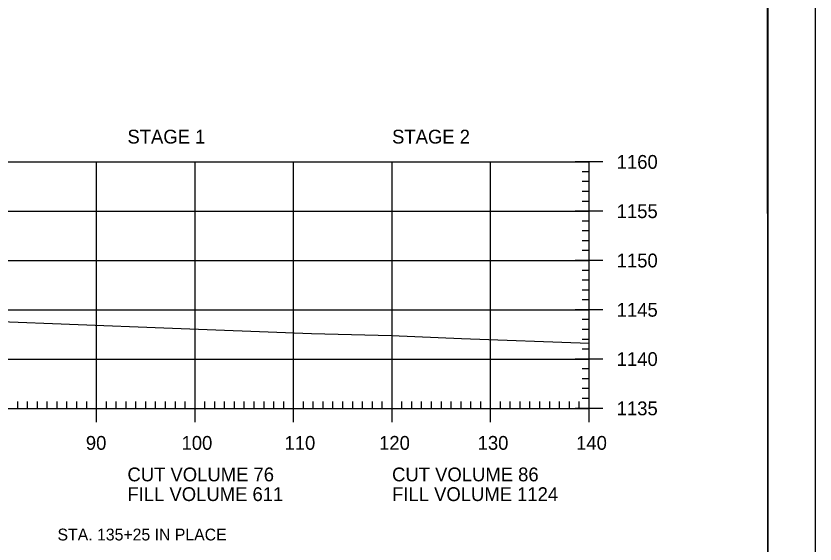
# Model space of a CAD drawing. Extents: x 1322838 to 1324533, y 339903 to 351025.
# Drawn here: x 1323785.5 to 1323866.6, y 342356.1 to 342409.6 of the extents above; entities that cross this region are included whole.
import ezdxf

# ---------------------------------------------------------------- set-up
doc = ezdxf.new("R2010")
doc.units = 0
for name, color, linetype in [('R_Axis', 7, 'Continuous'), ('R_Axis Annot', 7, 'Continuous'), ('R_Border', 7, 'Continuous'), ('R_Border Notes', 7, 'Continuous'), ('R_Exist Surface', 7, 'Continuous'), ('R_Grid', 7, 'Continuous'), ('R_No Plot', 7, 'Continuous')]:
    doc.layers.add(name, color=color, linetype=linetype)

msp = doc.modelspace()

# ---------------------------------------------------------------- linework, layer by layer
at = {"layer": 'R_Axis'}
for p, q in [((1323845.115, 342394.82), (1323842.315, 342394.82)), ((1323843.715, 342369.82), (1323843.715, 342394.82)), ((1323843.715, 342393.82), (1323843.015, 342393.82)), ((1323843.715, 342392.82), (1323843.015, 342392.82)), ((1323843.715, 342391.82), (1323843.015, 342391.82)), ((1323843.715, 342390.82), (1323843.015, 342390.82)), ((1323845.115, 342389.82), (1323842.315, 342389.82)), ((1323843.715, 342388.82), (1323843.015, 342388.82)), ((1323843.715, 342387.82), (1323843.015, 342387.82)), ((1323843.715, 342386.82), (1323843.015, 342386.82)), ((1323843.715, 342385.82), (1323843.015, 342385.82)), ((1323845.115, 342384.82), (1323842.315, 342384.82)), ((1323843.715, 342383.82), (1323843.015, 342383.82)), ((1323843.715, 342382.82), (1323843.015, 342382.82)), ((1323843.715, 342381.82), (1323843.015, 342381.82)), ((1323843.715, 342380.82), (1323843.015, 342380.82)), ((1323845.115, 342379.82), (1323842.315, 342379.82)), ((1323843.715, 342378.82), (1323843.015, 342378.82)), ((1323843.715, 342377.82), (1323843.015, 342377.82)), ((1323843.715, 342376.82), (1323843.015, 342376.82)), ((1323843.715, 342375.82), (1323843.015, 342375.82)), ((1323845.115, 342374.82), (1323842.315, 342374.82)), ((1323843.715, 342373.82), (1323843.015, 342373.82)), ((1323843.715, 342372.82), (1323843.015, 342372.82)), ((1323843.715, 342371.82), (1323843.015, 342371.82)), ((1323793.715, 342368.42), (1323793.715, 342371.22)), ((1323803.715, 342368.42), (1323803.715, 342371.22)), ((1323813.715, 342368.42), (1323813.715, 342371.22)), ((1323823.715, 342368.42), (1323823.715, 342371.22)), ((1323833.715, 342368.42), (1323833.715, 342371.22)), ((1323843.715, 342370.82), (1323843.015, 342370.82)), ((1323843.715, 342368.42), (1323843.715, 342371.22)), ((1323785.715, 342369.82), (1323785.715, 342370.52)), ((1323786.715, 342369.82), (1323786.715, 342370.52)), ((1323787.715, 342369.82), (1323787.715, 342370.52)), ((1323788.715, 342369.82), (1323788.715, 342370.52)), ((1323789.715, 342369.82), (1323789.715, 342370.52)), ((1323790.715, 342369.82), (1323790.715, 342370.52)), ((1323791.715, 342369.82), (1323791.715, 342370.52)), ((1323792.715, 342369.82), (1323792.715, 342370.52)), ((1323794.715, 342369.82), (1323794.715, 342370.52)), ((1323795.715, 342369.82), (1323795.715, 342370.52)), ((1323796.715, 342369.82), (1323796.715, 342370.52)), ((1323797.715, 342369.82), (1323797.715, 342370.52)), ((1323798.715, 342369.82), (1323798.715, 342370.52)), ((1323799.715, 342369.82), (1323799.715, 342370.52)), ((1323800.715, 342369.82), (1323800.715, 342370.52)), ((1323801.715, 342369.82), (1323801.715, 342370.52)), ((1323802.715, 342369.82), (1323802.715, 342370.52)), ((1323804.715, 342369.82), (1323804.715, 342370.52)), ((1323805.715, 342369.82), (1323805.715, 342370.52)), ((1323806.715, 342369.82), (1323806.715, 342370.52)), ((1323807.715, 342369.82), (1323807.715, 342370.52)), ((1323808.715, 342369.82), (1323808.715, 342370.52)), ((1323809.715, 342369.82), (1323809.715, 342370.52)), ((1323810.715, 342369.82), (1323810.715, 342370.52)), ((1323811.715, 342369.82), (1323811.715, 342370.52)), ((1323812.715, 342369.82), (1323812.715, 342370.52)), ((1323814.715, 342369.82), (1323814.715, 342370.52)), ((1323815.715, 342369.82), (1323815.715, 342370.52)), ((1323816.715, 342369.82), (1323816.715, 342370.52)), ((1323817.715, 342369.82), (1323817.715, 342370.52)), ((1323818.715, 342369.82), (1323818.715, 342370.52)), ((1323819.715, 342369.82), (1323819.715, 342370.52)), ((1323820.715, 342369.82), (1323820.715, 342370.52)), ((1323821.715, 342369.82), (1323821.715, 342370.52)), ((1323822.715, 342369.82), (1323822.715, 342370.52)), ((1323824.715, 342369.82), (1323824.715, 342370.52)), ((1323825.715, 342369.82), (1323825.715, 342370.52)), ((1323826.715, 342369.82), (1323826.715, 342370.52)), ((1323827.715, 342369.82), (1323827.715, 342370.52)), ((1323828.715, 342369.82), (1323828.715, 342370.52)), ((1323829.715, 342369.82), (1323829.715, 342370.52)), ((1323830.715, 342369.82), (1323830.715, 342370.52)), ((1323831.715, 342369.82), (1323831.715, 342370.52)), ((1323832.715, 342369.82), (1323832.715, 342370.52)), ((1323834.715, 342369.82), (1323834.715, 342370.52)), ((1323835.715, 342369.82), (1323835.715, 342370.52)), ((1323836.715, 342369.82), (1323836.715, 342370.52)), ((1323837.715, 342369.82), (1323837.715, 342370.52)), ((1323838.715, 342369.82), (1323838.715, 342370.52)), ((1323839.715, 342369.82), (1323839.715, 342370.52)), ((1323840.715, 342369.82), (1323840.715, 342370.52)), ((1323841.715, 342369.82), (1323841.715, 342370.52)), ((1323842.715, 342369.82), (1323842.715, 342370.52)), ((1323563.715, 342369.82), (1323843.715, 342369.82)), ((1323845.115, 342369.82), (1323842.315, 342369.82))]:
    msp.add_line(p, q, dxfattribs=at)
at = {"layer": 'R_Border'}
msp.add_line((1323861.895, 342253.82), (1323861.895, 342459.28), dxfattribs=at)
at = {"layer": 'R_Exist Surface'}
msp.add_lwpolyline([(1323783.124, 342378.678), (1323800.554, 342377.981), (1323815.543, 342377.428), (1323823.656, 342377.208), (1323830.772, 342376.914), (1323843.715, 342376.425)], dxfattribs=at)
at = {"layer": 'R_Grid'}
for p, q in [((1323563.715, 342394.82), (1323843.715, 342394.82)), ((1323793.715, 342369.82), (1323793.715, 342394.82)), ((1323803.715, 342369.82), (1323803.715, 342394.82)), ((1323813.715, 342369.82), (1323813.715, 342394.82)), ((1323823.715, 342369.82), (1323823.715, 342394.82)), ((1323833.715, 342369.82), (1323833.715, 342394.82)), ((1323843.715, 342369.82), (1323843.715, 342394.82)), ((1323563.715, 342389.82), (1323843.715, 342389.82)), ((1323563.715, 342384.82), (1323843.715, 342384.82)), ((1323563.715, 342379.82), (1323843.715, 342379.82)), ((1323563.715, 342374.82), (1323843.715, 342374.82)), ((1323563.715, 342369.82), (1323843.715, 342369.82))]:
    msp.add_line(p, q, dxfattribs=at)
at = {"layer": 'R_No Plot'}
for points in [[(1323533.308, 342463.175), (1323866.648, 342463.175), (1323866.648, 342249.837), (1323533.308, 342249.837)], [(1323779.635, 342459.28), (1323799.255, 342459.28), (1323799.255, 342449.4), (1323815.368, 342449.4), (1323838.567, 342449.4), (1323838.567, 342416.73), (1323861.775, 342416.73), (1323861.895, 342253.82), (1323545.715, 342253.82), (1323545.715, 342459.28)]]:
    msp.add_lwpolyline(points, close=True, dxfattribs=at)

# ---------------------------------------------------------------- texts
at = {"layer": 'R_Axis Annot'}
for s, p in [('STAGE 1', (1323796.852, 342396.682)), ('STAGE 2', (1323823.715, 342396.682)), ('1160', (1323846.515, 342394.12)), ('1155', (1323846.515, 342389.12)), ('1150', (1323846.515, 342384.12)), ('1145', (1323846.515, 342379.12)), ('1140', (1323846.515, 342374.12)), ('1135', (1323846.515, 342369.12)), ('90', (1323792.63, 342365.62)), ('100', (1323802.343, 342365.62)), ('110', (1323812.795, 342365.62)), ('120', (1323822.398, 342365.62)), ('130', (1323832.398, 342365.62)), ('140', (1323842.398, 342365.62)), ('CUT VOLUME 76', (1323796.852, 342362.42)), ('CUT VOLUME 86', (1323823.715, 342362.42)), ('FILL VOLUME 611', (1323796.852, 342360.42)), ('FILL VOLUME 1124', (1323823.715, 342360.42))]:
    msp.add_text(s, height=1.4, dxfattribs=at).set_placement(p)
at = {"layer": 'R_Border Notes'}
msp.add_text('STA. 135+25 IN PLACE ', height=1.19998, dxfattribs=at).set_placement((1323789.752, 342356.423))

doc.saveas('drawing.dxf')
